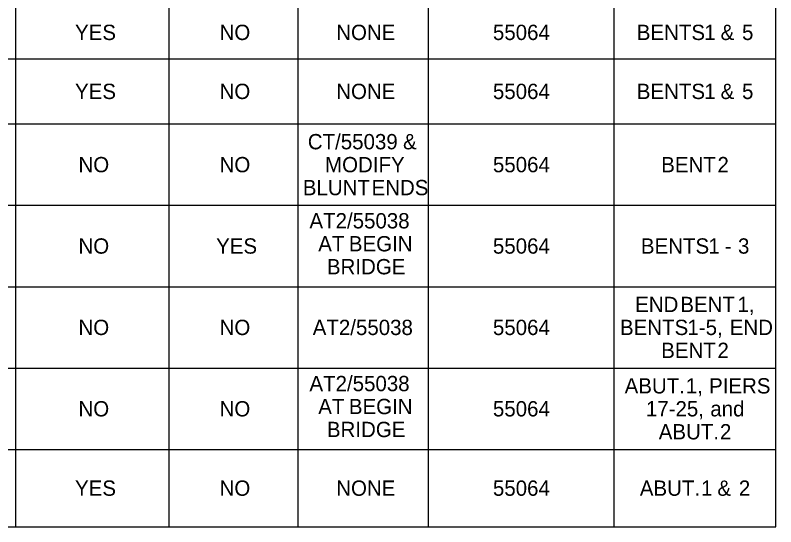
# Model space of a CAD drawing. Extents: x 16 to 1228740, y 11 to 152440.
# Drawn here: x 17.273 to 17.841, y 11.243 to 11.626 of the extents above; entities that cross this region are included whole.
import ezdxf

# ---------------------------------------------------------------- set-up
doc = ezdxf.new("R2010")
doc.units = 0
doc.layers.add('B_Text', color=7, linetype='Continuous')

msp = doc.modelspace()

# ---------------------------------------------------------------- linework, layer by layer
at = {"layer": 'B_Text'}
for p, q in [((17.27328, 11.24323), (17.27328, 11.95911)), ((17.38786, 11.24323), (17.38786, 11.95911)), ((17.48419, 11.24323), (17.48419, 11.95911)), ((17.58153, 11.24323), (17.58153, 11.95911)), ((17.72045, 11.24323), (17.72045, 11.95911)), ((17.84112, 11.24323), (17.84112, 11.95911)), ((16.35459, 11.59306), (17.84112, 11.59306)), ((16.35459, 11.54439), (17.84112, 11.54439)), ((16.35459, 11.48355), (17.84112, 11.48355)), ((16.35459, 11.42271), (17.84112, 11.42271)), ((16.35459, 11.36187), (17.84112, 11.36187)), ((16.35459, 11.30103), (17.84112, 11.30103)), ((16.35459, 11.24323), (17.84112, 11.24323))]:
    msp.add_line(p, q, dxfattribs=at)

# ---------------------------------------------------------------- texts
for s, p in [('YES', (17.31744, 11.60711)), ('NO', (17.42546, 11.60711)), ('NONE', (17.51263, 11.60711)), ('55064', (17.62973, 11.60711)), ('BENTS', (17.73725, 11.60711)), (' 1', (17.7834, 11.60711)), (' &', (17.79563, 11.60711)), (' 5', (17.81164, 11.60711)), ('YES', (17.31744, 11.563)), ('NO', (17.42546, 11.563)), ('NONE', (17.51263, 11.563)), ('55064', (17.62973, 11.563)), ('BENTS', (17.73725, 11.563)), (' 1', (17.7834, 11.563)), (' &', (17.79563, 11.563)), (' 5', (17.81164, 11.563)), ('CT/55039', (17.49139, 11.52541)), (' &', (17.55832, 11.52541)), ('NO', (17.32001, 11.50825)), ('NO', (17.42546, 11.50825)), ('MODIFY', (17.50428, 11.50825)), ('55064', (17.62973, 11.50825)), ('BENT', (17.75549, 11.50825)), (' 2', (17.79328, 11.50825)), ('BLUNT', (17.48767, 11.49109)), (' ENDS', (17.53477, 11.49109)), ('AT2/55038', (17.49261, 11.46628)), ('NO', (17.32001, 11.44741)), ('YES', (17.42289, 11.44741)), ('AT', (17.49919, 11.44912)), (' BEGIN', (17.51781, 11.44912)), ('55064', (17.62973, 11.44741)), ('BENTS', (17.74032, 11.44741)), (' 1', (17.78648, 11.44741)), (' 3', (17.80864, 11.44741)), (' -', (17.79871, 11.44741)), ('BRIDGE', (17.50567, 11.43196)), ('END', (17.73601, 11.40373)), (' BENT', (17.76552, 11.40373)), (' 1,', (17.80822, 11.40373)), ('NO', (17.32001, 11.38657)), ('NO', (17.42546, 11.38657)), ('AT2/55038', (17.49507, 11.38657)), ('55064', (17.62973, 11.38657)), ('BENTS', (17.72468, 11.38657)), (' 1-5,', (17.77084, 11.38657)), (' END', (17.80247, 11.38657)), ('BENT', (17.75549, 11.36941)), (' 2', (17.79328, 11.36941)), ('AT2/55038', (17.49261, 11.3446)), ('ABUT.', (17.72816, 11.34289)), (' 1,', (17.76966, 11.34289)), (' PIERS', (17.787, 11.34289)), ('NO', (17.32001, 11.32573)), ('NO', (17.42546, 11.32573)), ('AT', (17.49919, 11.32744)), (' BEGIN', (17.51781, 11.32744)), ('55064', (17.62973, 11.32573)), ('17-25,', (17.74405, 11.32573)), (' and', (17.78793, 11.32573)), ('BRIDGE', (17.50567, 11.31028)), ('ABUT.', (17.75363, 11.30857)), (' 2', (17.79514, 11.30857)), ('YES', (17.31744, 11.26641)), ('NO', (17.42546, 11.26641)), ('NONE', (17.51263, 11.26641)), ('55064', (17.62973, 11.26641)), ('ABUT.', (17.73951, 11.26641)), (' 1', (17.78102, 11.26641)), (' &', (17.79324, 11.26641)), (' 2', (17.80926, 11.26641))]:
    msp.add_text(s, height=0.01144, dxfattribs=at).set_placement(p)

doc.saveas('drawing.dxf')
